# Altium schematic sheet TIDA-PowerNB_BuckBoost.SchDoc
size A3; Date: Not shown in title block; ApprovedBy: Not shown in title block; CheckedBy: Not shown in title block; Author: Not shown in title block; CompanyName: Not shown in title block; DrawnBy: Julian Hagedorn; Engineer: Not shown in title block; Organization: Not shown in title block; Address1: Not shown in title block; Address2: Not shown in title block; Address3: Not shown in title block; Address4: Not shown in title block; DocumentNumber: 1; Revision: Use project parameter SCH_Rev; SheetNumber: 1; SheetTotal: 2; PageSetup: Record=PageOptions¦CenterHorizontal=True¦CenterVertical=True¦PrintScale=1.00¦XCorrection=1.00¦YCorrection=1.00¦PrintKind=0¦BorderSize=5000000¦LeftOffset=0¦BottomOffset=0¦Orientation=2¦PaperLength=1000¦PaperWidth=1000¦Scale=100¦PaperSource=15¦PrintQuality=600¦MediaType=1¦DitherType=10¦PaperKind=Letter¦PrintScaleMode=1
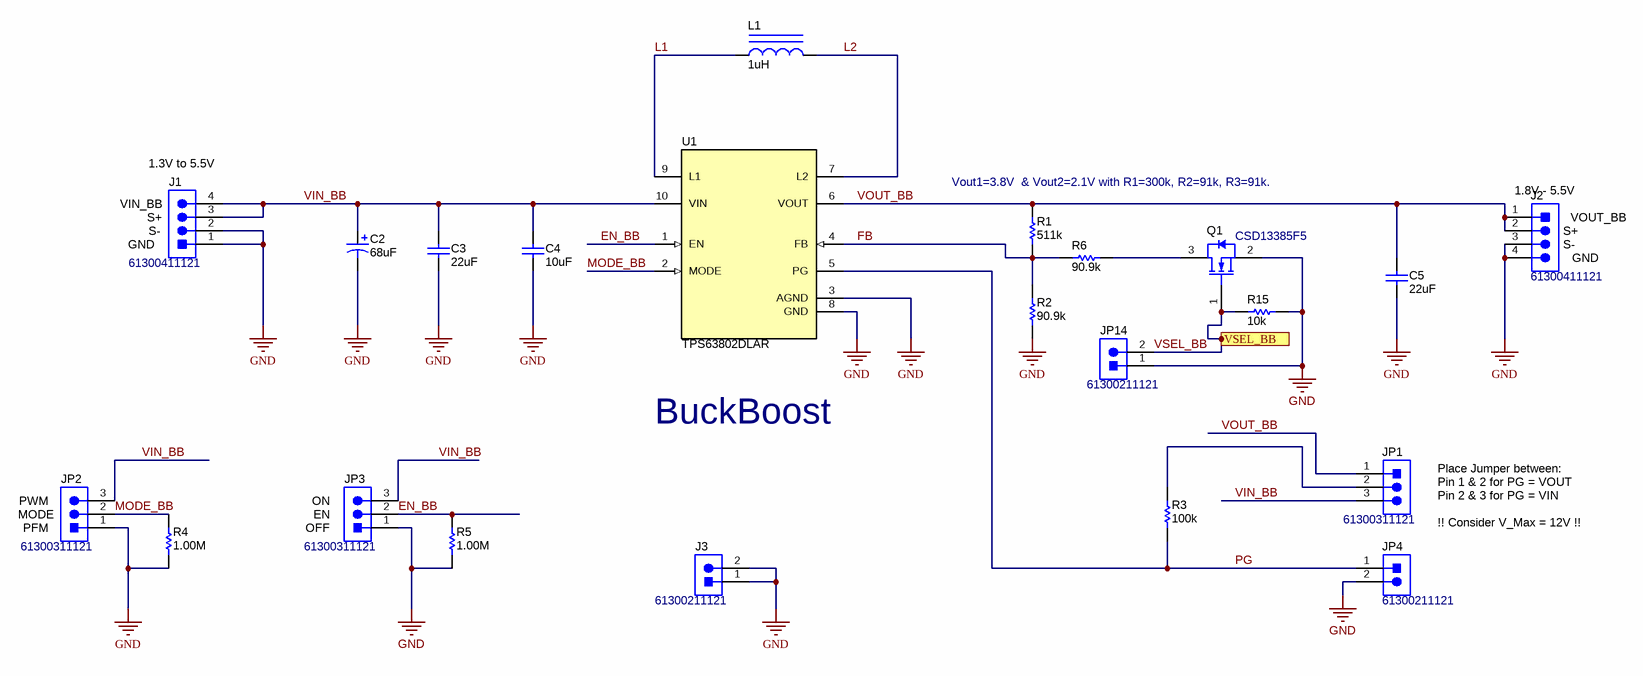
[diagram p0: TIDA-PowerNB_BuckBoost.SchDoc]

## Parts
C2  ValueDisplayed: 68uF  [7343-31]  (hidden comment: Cap_Polarized)
C3  ValueDisplayed: 22uF  [1206_190]  (hidden comment: Capacitor)
C4  ValueDisplayed: 10uF  [0603S]  (hidden comment: Capacitor)
C5  ValueDisplayed: 22uF  [0603S]  (hidden comment: Capacitor)
J1  61300411121  [WURTH_61300411121]
J2  61300411121  [WURTH_61300411121]
J3  61300211121  [WURTH_61300211121]
JP1  61300311121  [WURTH_61300311121]
JP2  61300311121  [WURTH_61300311121]
JP3  61300311121  [WURTH_61300311121]
JP4  61300211121  [WURTH_61300211121]
JP14  61300211121  [WURTH_61300211121]
L1  ValueDisplayed: 1uH  [WE-MAPI_4020]  (hidden comment: 74438356010)
Q1  CSD13385F5  [YJK0003A]
R1  ValueDisplayed: 511k  [0402]  (hidden comment: CRCW0402511KFKED)
R2  ValueDisplayed: 90.9k  [0402]  (hidden comment: CRCW040290K9FKED)
R3  ValueDisplayed: 100k  [0402]  (hidden comment: RC0402FR-07100KL)
R4  ValueDisplayed: 1.00M  [0402]  (hidden comment: CRCW04021M00FKED)
R5  ValueDisplayed: 1.00M  [0402]  (hidden comment: CRCW04021M00FKED)
R6  ValueDisplayed: 90.9k  [0402]  (hidden comment: CRCW040290K9FKED)
R15  Res_ohm: 10k  [0402]  (hidden comment: ERJ-2RKF1002X)
U1  TPS63802DLAR  [DLA0010A]

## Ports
VSEL_BB

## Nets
GND: C2.2(-) C3.2 C4.2 C5.2 J1.1 J1.2 J2.3 J2.4 J3.1 J3.2 JP2.1 JP3.1 JP4.2 JP14.1 Q1.2(S) R2.1 R4.1 R5.1 R15.1 U1.3(AGND) U1.8(GND)
EN_BB: JP3.2 R5.2 U1.1(EN)
FB: R1.1 R2.2 R6.2 U1.4(FB)
L1: L1.1 U1.9(L1)
L2: L1.2 U1.7(L2)
MODE_BB: JP2.2 R4.2 U1.2(MODE)
PG: JP4.1 R3.1 U1.5(PG)
VIN_BB: C2.1(+) C3.1 C4.1 J1.3 J1.4 JP1.3 JP2.3 JP3.3 U1.10(VIN)
VOUT_BB: C5.1 J2.1 J2.2 JP1.1 R1.2 U1.6(VOUT)
VSEL_BB: JP14.2 Q1.1(G) R15.2 ; port VSEL_BB
NetJP1_2: JP1.2 R3.2
NetQ1_3: Q1.3(D) R6.1

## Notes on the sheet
- (near J1) 1.3V to 5.5V
- (near J1) VIN_BB
- (near J1) S+
- (near J1) S-
- (near R1) Vout1=3.8V  & Vout2=2.1V with R1=300k, R2=91k, R3=91k.
- (near J2) 1.8V - 5.5V
- (near J2) S+
- (near J2) VOUT_BB
- (near J1) GND
- (near J2) S-
- (near J2) GND
- BuckBoost
- (near JP2) PWM
- (near JP3) ON
- (near JP2) PFM
- (near JP2) MODE
- (near JP3) OFF
- (near JP3) EN
- Place Jumper between:
  Pin 1 & 2 for PG = VOUT
  Pin 2 & 3 for PG = VIN
  !! Consider V_Max = 12V !!

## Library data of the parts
C2 = CMP-0011790-2: CAP, TA, 68 uF, 20 V, +/- 10%, 0.15 ohm, SMD; PartNumber: T495D686K020ATE150; Manufacturer: Kemet; Polarized: Y; CompType: Capacitor; Value: 68uF; U/M: EA; Cap_F: 68µF; VDC_V: 20V; ESR_ohm: 1.5d; IRMS_A: 9dA; TaMin_C: -55°C; TaMax_C: 125°C; Cap_Case: D; AEC Category: Q200; SizeArea_mm2: 31.39; SizeAreaWB_mm2: 58.59; SizeX_mm: 7.3; SizeY_mm: 4.3; SizeZ_mm: 3.1
C3 = CMP-0009024-2: CAP, CERM, 22 uF, 25 V, +/- 20%, X5R, 1206_190; PartNumber: TMK316BBJ226ML-T; Manufacturer: Taiyo Yuden; Polarized: N; Value: 22uF; U/M: EA; Cap_F: 22µF; Value1: Unknown; VDC_V: 25V; TaMin_C: -55°C; TaMax_C: 85°C; Cap_Case: 1206; AEC Category: Q200; SizeArea_mm2: 5.12; SizeAreaWB_mm2: 10.92; SizeX_mm: 3.2; SizeY_mm: 1.6; SizeZ_mm: 1.9
C4 = CMP-0007304-5: CAP, CERM, 10 uF, 6.3 V, +/- 20%, X5R, 0603; PartNumber: GRM188R60J106ME84; Manufacturer: MuRata; Polarized: N; Value: 10uF; U/M: EA; Cap_F: 10µF; Value1: Unknown; VDC_V: 6.3V; TaMin_C: -55°C; TaMax_C: 85°C; Cap_Case: 0603; SizeArea_mm2: 1.28; SizeAreaWB_mm2: 4.68; SizeX_mm: 1.6; SizeY_mm: 0.8; SizeZ_mm: 1; AEC Category: Q200
C5 = CMP-0007306-5: CAP, CERM, 22 uF, 6.3 V, +/- 20%, X5R, 0603; PartNumber: GRM188R60J226MEA0D; Manufacturer: MuRata; Polarized: N; Value: 22uF; U/M: EA; Cap_F: 22µF; Value1: Unknown; VDC_V: 6.3V; TaMin_C: -55°C; TaMax_C: 85°C; Cap_Case: 0603; SizeArea_mm2: 1.28; SizeAreaWB_mm2: 4.68; SizeX_mm: 1.6; SizeY_mm: 0.8; SizeZ_mm: 1; AEC Category: Q200
J1 J2 = CMP-0054798-2: Header, 2.54 mm, 4x1, Gold, TH; Manufacturer: Wurth Elektronik; Pitch_mm: 2.54; Gender: Male; Row_Count: 1; Cert_UL: Y; Shrouded: N
J3 JP4 JP14 = CMP-0054794-2: Header, 2.54 mm, 2x1, Gold, TH; Manufacturer: Wurth Elektronik; Shrouded: N; Gender: Male; Green_REACh: Passed; Pitch_mm: 2.54; Green_Lifecycle: Active; Row_Count: 1; Cert_UL: Y
JP1-JP3 = CMP-0054796-2: Header, 2.54 mm, 3x1, Gold, TH; Manufacturer: Wurth Elektronik; Pitch_mm: 2.54; Green_Lifecycle: Active; Cert_UL: Y; Shrouded: N; Green_REACh: Passed; Gender: Male; Row_Count: 1
L1 = CMP-0064168-1: Inductor, Shielded, 1 uH, 7.2 A, 0.012 ohm, SMD; Manufacturer: Wurth Elektronik; Isat: 9A @ 20% inductance drop; Irms: 7.2A @ 40C rise; Green_Lifecycle: Active; SizeAreaWB_mm2: 26.01; DCR_ohm: 0.012; Green_REACh: Passed; Value: 1uH; Imax_A: 7.2A; SizeZ_mm: 2.1; SizeX_mm: 4.1; SizeArea_mm2: 16.81; Ind_H: 1µH; AEC Qualified: N; AEC Category: Q200
Q1 = CMP-0080799-1: MOSFET, N-CH, 12 V, 4.3 A, YJK0003A (PICOSTAR-3); Alternate Manufacturer: None; Manufacturer: Texas Instruments; Rdson45_ohm: 0.019; QgTyp_nC: 3.9; SizeAreaWB_mm2: 4.3077; Vgs_V: 8V; Value1: 0.019 ohm; VdsMax_V: 12V; Value: 12V; IdsMax_A: 4.3A; SizeZ_mm: 0.35; SizeX_mm: 1.49; SizeY_mm: 0.73; Value2: 3.9 nC; SizeArea_mm2: 1.0877; ChType: N; AEC Category: Q101
R1 = CMP-0026435-2: RES, 511 k, 1%, 0.063 W, AEC-Q200 Grade 0, 0402; Manufacturer: Vishay-Dale; Power_W: 63mW; TempCo: 100 ppm/C; Value: 511k; EIA_Code: E96; SizeX_mm: 1; SizeY_mm: 0.5; SizeZ_mm: 0.6; Value2: 0.063W; AEC Qualified: Y; VDC_V: 50V; AEC Category: Q200; AEC Grade: 0
R2 R6 = CMP-0026605-2: RES, 90.9 k, 1%, 0.063 W, AEC-Q200 Grade 0, 0402; Manufacturer: Vishay-Dale; Power_W: 63mW; TempCo: 100 ppm/C; Value_Code: 90k9; Value: 90.9k; EIA_Code: E96; SizeX_mm: 1; SizeY_mm: 0.5; SizeZ_mm: 0.6; Value2: 0.063W; AEC Qualified: Y; VDC_V: 50V; AEC Category: Q200; AEC Grade: 0
R3 = CMP-0026721-1: RES, 100 k, 1%, 0.0625 W, 0402; Manufacturer: Yageo America; Power_W: 62.5mW; TempCo: 100 ppm/C; U/M: EA; Value: 100k; EIA_Code: E96; SizeX_mm: 1; SizeY_mm: 0.5; SizeZ_mm: 0.6; AEC Qualified: N; VDC_V: 50V; AEC Category: Q200
R4 R5 = CMP-0026100-2: RES, 1.00 M, 1%, 0.063 W, AEC-Q200 Grade 0, 0402; Manufacturer: Vishay-Dale; Power_W: 63mW; TempCo: 100 ppm/C; Value_Code: 1M00; Value: 1.00Meg; EIA_Code: E96; Res_ohm: 1M; SizeX_mm: 1; SizeY_mm: 0.5; SizeZ_mm: 0.6; Value2: 0.063W; AEC Qualified: Y; VDC_V: 50V; AEC Category: Q200; AEC Grade: 0
R15 = CMP-0026658-1: RES, 10.0 k, 1%, 0.1 W, 0402; Manufacturer: Panasonic; Power_W: 100mW; TempCo: 100 ppm/C; Value_Code: 10k0; U/M: EA; Value: 10.0k; EIA_Code: E96; SizeX_mm: 1; SizeY_mm: 0.5; SizeZ_mm: 0.6; Value2: 0.1W; CompType: Resistor; VDC_V: 50V; AEC Category: Q200
U1 = CMP-0076712-3: High Current, High Efficiency Single Inductor Buck-Boost Converter, DLA0010A (VQFN-HR-10); Manufacturer: Texas Instruments; Alternate PartNumber: TPS63802DLAT; SizeX_mm: 2.0; SizeY_mm: 3.0; CompType: IC; SizeZ_mm: 1.0; SizeArea_mm2: 6.0; SizeAreaWB_mm2: 12.0; U/M: EA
